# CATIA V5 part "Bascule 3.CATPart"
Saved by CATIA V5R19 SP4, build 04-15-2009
Part number: Bascule 3
Bounding box of the stored display mesh (mm): x -5 to 35, y -14.997 to 48.373, z -164.99 to 164.99
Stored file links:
  D:\thinkmotion-MPB\CIAO82010_JCF\PLANTECOSTE\0593\assemblage 593\Bascule 3.CATPart
  D:\thinkmotion-MPB\CIAO82010_JCF\PLANTECOSTE\0593\assemblage 593\593-Plantecoste.CATProduct
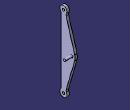
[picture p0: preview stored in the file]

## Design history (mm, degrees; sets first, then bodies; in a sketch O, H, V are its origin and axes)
External parameters (linked from other documents)
  `External.Diamètre axe` = 10 mm
  External.Longueur.1 = 300 mm
Body1 (main body)
  Sketch1 on yz-plane, origin (0, 0, 0), H (0, 1, 0), V (0, 0, 1)
    construction line L1 (0, 0) -> (0, 224.242)
    circle A1 centre (0, 150) radius 5
    point P2 (0, 150)
    line L2 (-10, 138.8197) -> (-10, 0)
    point P3 (-10, 0)
    line L3 (10, 138.8197) -> (50, 0)
    arc A2 centre (0, 150) radius 15 from (10, 138.8197) to (-10, 138.8197) ccw
    point P4 (-10, 138.8197)
    point P5 (-10, 138.8197)
    point P6 (10, 138.8197)
    point P7 (10, 138.8197)
    construction line L4 through (16.3046, 0) direction (1, 0)
    point P10 (-10, 0)
    point P11 (50, 0)
    point P12 (-10, 0)
    point P13 (-10, 0)
    point P14 (-10, -138.8197)
    line L5 (-10, -138.8197) -> (-10, 0)
    point P15 (-10, -138.8197)
    point P16 (10, -138.8197)
    arc A3 centre (0, -150) radius 15 from (10, -138.8197) to (-10, -138.8197) cw
    point P18 (50, 0)
    point P19 (10, -138.8197)
    line L6 (10, -138.8197) -> (50, 0)
    circle A4 centre (0, -150) radius 5
    radius A1 = 5 {= `External.Diamètre axe` /2}
    radius A2 = 15 {= `External.Diamètre axe` *1.5}
    distance L1 L2 = 10 {= `External.Diamètre axe`}
    distance P2 L4 = 150 {= External.Longueur.1 /2}
    distance L1 P6 = 10 {= `External.Diamètre axe`}
    distance P11 L5 = 60 {= `External.Diamètre axe` *6}
    vertical: L1 V, L2 V
    coincidence: P2 L1, P7 P6, P5 P4, P11 L4, L4 H, P3 L4
    symmetry: P3 P13 L4, P5 P14 L4, L2 L5 L4, P4 P15 L4, P6 P16 L4, A2 A3 L4, P11 P18 L4, P7 P19 L4, L3 L6 L4, A1 A4 L4
  Pad1: profile Sketch1, direction (1, 0, 0), length 5, opposite side length 5
  Fillet1: radius 10 {= `External.Diamètre axe`}, on edge [face of Pad1 from Sketch1.A3 | face of Pad1 from Sketch1.L5]; edge [face of Pad1 from Sketch1.L6 | face of Pad1 from Sketch1.A3]; edge [face of Pad1 from Sketch1.A2 | face of Pad1 from Sketch1.L3]; edge [face of Pad1 from Sketch1.L2 | face of Pad1 from Sketch1.A2]
  Fillet2: radius 40 {= `External.Diamètre axe` *4}, on edge [face of Pad1 from Sketch1.L3 | face of Pad1 from Sketch1.L6]
  Sketch2 on end face of Pad1, origin (5, 0, 0), H (0, 1, 0), V (0, 0, 1)
    circle A1 centre (35, 0) radius 5
    point P1 (35, 0)
    distance P1 V = 35 {= `External.Diamètre axe` *3.5}
    radius A1 = 5 {= `External.Diamètre axe` /2}
    coincidence: P1 H
  Pad2: profile Sketch2, direction (1, 0, 0), length 30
